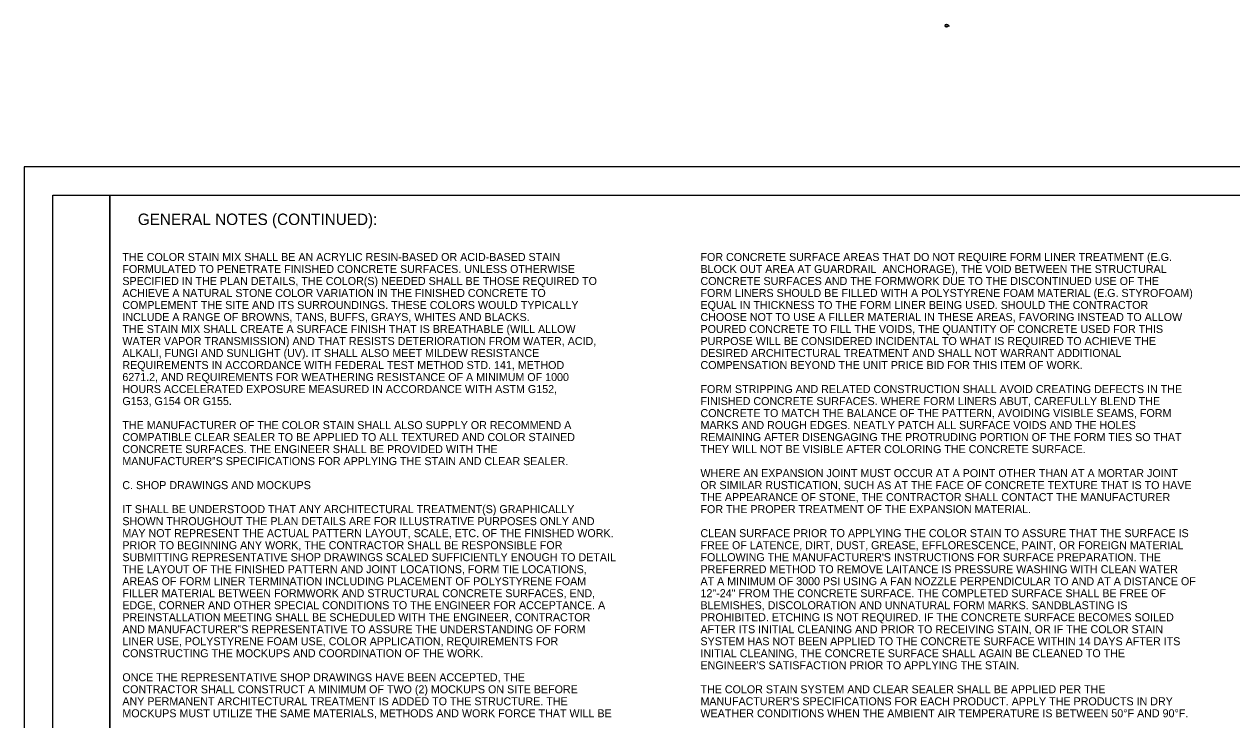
# Model space of a CAD drawing. Extents: x 0 to 442, y -31 to 24.
# Drawn here: x 0 to 21.13, y 12.33 to 24.49 of the extents above; entities that cross this region are included whole.
import ezdxf

# ---------------------------------------------------------------- set-up
doc = ezdxf.new("R2010")
doc.units = 0
for name, color, linetype in [('Default', 7, 'Continuous'), ('SH_Border', 7, 'Continuous'), ('SH_Cut_Line', 7, 'Continuous'), ('SH_Text', 7, 'Continuous')]:
    doc.layers.add(name, color=color, linetype=linetype)

msp = doc.modelspace()

# ---------------------------------------------------------------- linework, layer by layer
at = {"layer": 'Default'}
for p, q in [((16.11, 24.467), (16.163, 24.467)), ((16.137, 24.467), (16.186, 24.467))]:
    msp.add_line(p, q, dxfattribs=at)
msp.add_circle((16.137, 24.467), 0.026, dxfattribs=at)
at = {"layer": 'SH_Border'}
for points in [[(0.5, 21.5), (1.5, 21.5), (1.5, 0.5), (0.5, 0.5)], [(1.5, 21.5), (33.5, 21.5), (33.5, 0.5), (1.5, 0.5)]]:
    msp.add_lwpolyline(points, close=True, dxfattribs=at)
at = {"layer": 'SH_Cut_Line'}
msp.add_lwpolyline([(0, 0), (34, 0), (34, 22), (0, 22)], close=True, dxfattribs=at)

# ---------------------------------------------------------------- texts
at = {"layer": 'Default'}
for s, height, p in [('P.27', 0.00328, (16.132, 24.457)), ('1', 0.00328, (16.136, 24.474)), ('Drawing', 0.00328, (16.169, 24.474)), ('1:1', 0.00328, (16.169, 24.457)), ('THE COLOR STAIN MIX SHALL BE AN ACRYLIC RESIN-BASED OR ACID-BASED STAIN', 0.14, (1.718, 20.352)), ('FOR CONCRETE SURFACE AREAS THAT DO NOT REQUIRE FORM LINER TREATMENT (E.G.', 0.14, (11.831, 20.352)), ('FORMULATED TO PENETRATE FINISHED CONCRETE SURFACES. UNLESS OTHERWISE', 0.14, (1.718, 20.142)), ('BLOCK OUT AREA AT GUARDRAIL  ANCHORAGE), THE VOID BETWEEN THE STRUCTURAL ', 0.14, (11.831, 20.142)), ('SPECIFIED IN THE PLAN DETAILS, THE COLOR(S) NEEDED SHALL BE THOSE REQUIRED TO ', 0.14, (1.718, 19.932)), ('CONCRETE SURFACES AND THE FORMWORK DUE TO THE DISCONTINUED USE OF THE ', 0.14, (11.831, 19.932)), ('ACHIEVE A NATURAL STONE COLOR VARIATION IN THE FINISHED CONCRETE TO', 0.14, (1.718, 19.722)), ('FORM LINERS SHOULD BE FILLED WITH A POLYSTYRENE FOAM MATERIAL (E.G. STYROFOAM) ', 0.14, (11.831, 19.722)), ('COMPLEMENT THE SITE AND ITS SURROUNDINGS. THESE COLORS WOULD TYPICALLY', 0.14, (1.718, 19.512)), ('EQUAL IN THICKNESS TO THE FORM LINER BEING USED. SHOULD THE CONTRACTOR ', 0.14, (11.831, 19.512)), ('INCLUDE A RANGE OF BROWNS, TANS, BUFFS, GRAYS, WHITES AND BLACKS.', 0.14, (1.718, 19.302)), ('CHOOSE NOT TO USE A FILLER MATERIAL IN THESE AREAS, FAVORING INSTEAD TO ALLOW ', 0.14, (11.831, 19.302)), ('THE STAIN MIX SHALL CREATE A SURFACE FINISH THAT IS BREATHABLE (WILL ALLOW', 0.14, (1.718, 19.092)), ('POURED CONCRETE TO FILL THE VOIDS, THE QUANTITY OF CONCRETE USED FOR THIS ', 0.14, (11.831, 19.092)), ('WATER VAPOR TRANSMISSION) AND THAT RESISTS DETERIORATION FROM WATER, ACID,', 0.14, (1.718, 18.882)), ('PURPOSE WILL BE CONSIDERED INCIDENTAL TO WHAT IS REQUIRED TO ACHIEVE THE ', 0.14, (11.831, 18.882)), ('ALKALI, FUNGI AND SUNLIGHT (UV). IT SHALL ALSO MEET MILDEW RESISTANCE', 0.14, (1.718, 18.672)), ('DESIRED ARCHITECTURAL TREATMENT AND SHALL NOT WARRANT ADDITIONAL ', 0.14, (11.831, 18.672)), ('REQUIREMENTS IN ACCORDANCE WITH FEDERAL TEST METHOD STD. 141, METHOD', 0.14, (1.718, 18.462)), ('COMPENSATION BEYOND THE UNIT PRICE BID FOR THIS ITEM OF WORK.', 0.14, (11.831, 18.462)), ('6271.2, AND REQUIREMENTS FOR WEATHERING RESISTANCE OF A MINIMUM OF 1000', 0.14, (1.718, 18.252)), ('HOURS ACCELERATED EXPOSURE MEASURED IN ACCORDANCE WITH ASTM G152,', 0.14, (1.718, 18.042)), ('FORM STRIPPING AND RELATED CONSTRUCTION SHALL AVOID CREATING DEFECTS IN THE ', 0.14, (11.831, 18.042)), ('G153, G154 OR G155.', 0.14, (1.718, 17.832)), ('FINISHED CONCRETE SURFACES. WHERE FORM LINERS ABUT, CAREFULLY BLEND THE ', 0.14, (11.831, 17.832)), ('CONCRETE TO MATCH THE BALANCE OF THE PATTERN, AVOIDING VISIBLE SEAMS, FORM', 0.14, (11.831, 17.622)), ('THE MANUFACTURER OF THE COLOR STAIN SHALL ALSO SUPPLY OR RECOMMEND A', 0.14, (1.718, 17.412)), ('MARKS AND ROUGH EDGES. NEATLY PATCH ALL SURFACE VOIDS AND THE HOLES ', 0.14, (11.831, 17.412)), ('COMPATIBLE CLEAR SEALER TO BE APPLIED TO ALL TEXTURED AND COLOR STAINED', 0.14, (1.718, 17.202)), ('REMAINING AFTER DISENGAGING THE PROTRUDING PORTION OF THE FORM TIES SO THAT ', 0.14, (11.831, 17.202)), ('CONCRETE SURFACES. THE ENGINEER SHALL BE PROVIDED WITH THE', 0.14, (1.718, 16.992)), ('THEY WILL NOT BE VISIBLE AFTER COLORING THE CONCRETE SURFACE.', 0.14, (11.831, 16.992)), ('MANUFACTURER‟S SPECIFICATIONS FOR APPLYING THE STAIN AND CLEAR SEALER.', 0.14, (1.718, 16.782)), ('WHERE AN EXPANSION JOINT MUST OCCUR AT A POINT OTHER THAN AT A MORTAR JOINT ', 0.14, (11.831, 16.572)), ('C. SHOP DRAWINGS AND MOCKUPS', 0.14, (1.718, 16.362)), ('OR SIMILAR RUSTICATION, SUCH AS AT THE FACE OF CONCRETE TEXTURE THAT IS TO HAVE ', 0.14, (11.831, 16.362)), ('THE APPEARANCE OF STONE, THE CONTRACTOR SHALL CONTACT THE MANUFACTURER ', 0.14, (11.831, 16.152)), ('IT SHALL BE UNDERSTOOD THAT ANY ARCHITECTURAL TREATMENT(S) GRAPHICALLY ', 0.14, (1.718, 15.942)), ('FOR THE PROPER TREATMENT OF THE EXPANSION MATERIAL.', 0.14, (11.831, 15.942)), ('SHOWN THROUGHOUT THE PLAN DETAILS ARE FOR ILLUSTRATIVE PURPOSES ONLY AND ', 0.14, (1.718, 15.732)), ('MAY NOT REPRESENT THE ACTUAL PATTERN LAYOUT, SCALE, ETC. OF THE FINISHED WORK. ', 0.14, (1.718, 15.522)), ('CLEAN SURFACE PRIOR TO APPLYING THE COLOR STAIN TO ASSURE THAT THE SURFACE IS ', 0.14, (11.831, 15.522)), ('PRIOR TO BEGINNING ANY WORK, THE CONTRACTOR SHALL BE RESPONSIBLE FOR ', 0.14, (1.718, 15.312)), ('FREE OF LATENCE, DIRT, DUST, GREASE, EFFLORESCENCE, PAINT, OR FOREIGN MATERIAL ', 0.14, (11.831, 15.312)), ('SUBMITTING REPRESENTATIVE SHOP DRAWINGS SCALED SUFFICIENTLY ENOUGH TO DETAIL ', 0.14, (1.718, 15.102)), ("FOLLOWING THE MANUFACTURER'S INSTRUCTIONS FOR SURFACE PREPARATION. THE ", 0.14, (11.831, 15.102)), ('THE LAYOUT OF THE FINISHED PATTERN AND JOINT LOCATIONS, FORM TIE LOCATIONS, ', 0.14, (1.718, 14.892)), ('PREFERRED METHOD TO REMOVE LAITANCE IS PRESSURE WASHING WITH CLEAN WATER ', 0.14, (11.831, 14.892)), ('AREAS OF FORM LINER TERMINATION INCLUDING PLACEMENT OF POLYSTYRENE FOAM ', 0.14, (1.718, 14.682)), ('AT A MINIMUM OF 3000 PSI USING A FAN NOZZLE PERPENDICULAR TO AND AT A DISTANCE OF ', 0.14, (11.831, 14.682)), ('FILLER MATERIAL BETWEEN FORMWORK AND STRUCTURAL CONCRETE SURFACES, END, ', 0.14, (1.718, 14.472)), ('12"-24" FROM THE CONCRETE SURFACE. THE COMPLETED SURFACE SHALL BE FREE OF ', 0.14, (11.831, 14.472)), ('EDGE, CORNER AND OTHER SPECIAL CONDITIONS TO THE ENGINEER FOR ACCEPTANCE. A ', 0.14, (1.718, 14.262)), ('BLEMISHES, DISCOLORATION AND UNNATURAL FORM MARKS. SANDBLASTING IS ', 0.14, (11.831, 14.262)), ('PREINSTALLATION MEETING SHALL BE SCHEDULED WITH THE ENGINEER, CONTRACTOR ', 0.14, (1.718, 14.052)), ('PROHIBITED. ETCHING IS NOT REQUIRED. IF THE CONCRETE SURFACE BECOMES SOILED ', 0.14, (11.831, 14.052)), ('AND MANUFACTURER‟S REPRESENTATIVE TO ASSURE THE UNDERSTANDING OF FORM ', 0.14, (1.718, 13.842)), ('AFTER ITS INITIAL CLEANING AND PRIOR TO RECEIVING STAIN, OR IF THE COLOR STAIN ', 0.14, (11.831, 13.842)), ('LINER USE, POLYSTYRENE FOAM USE, COLOR APPLICATION, REQUIREMENTS FOR ', 0.14, (1.718, 13.632)), ('SYSTEM HAS NOT BEEN APPLIED TO THE CONCRETE SURFACE WITHIN 14 DAYS AFTER ITS ', 0.14, (11.831, 13.632)), ('CONSTRUCTING THE MOCKUPS AND COORDINATION OF THE WORK.', 0.14, (1.718, 13.422)), ('INITIAL CLEANING, THE CONCRETE SURFACE SHALL AGAIN BE CLEANED TO THE ', 0.14, (11.831, 13.422)), ("ENGINEER'S SATISFACTION PRIOR TO APPLYING THE STAIN.", 0.14, (11.831, 13.212)), ('ONCE THE REPRESENTATIVE SHOP DRAWINGS HAVE BEEN ACCEPTED, THE', 0.14, (1.718, 13.002)), ('CONTRACTOR SHALL CONSTRUCT A MINIMUM OF TWO (2) MOCKUPS ON SITE BEFORE', 0.14, (1.718, 12.792)), ('THE COLOR STAIN SYSTEM AND CLEAR SEALER SHALL BE APPLIED PER THE ', 0.14, (11.831, 12.792)), ('ANY PERMANENT ARCHITECTURAL TREATMENT IS ADDED TO THE STRUCTURE. THE', 0.14, (1.718, 12.582)), ("MANUFACTURER'S SPECIFICATIONS FOR EACH PRODUCT. APPLY THE PRODUCTS IN DRY ", 0.14, (11.831, 12.582)), ('MOCKUPS MUST UTILIZE THE SAME MATERIALS, METHODS AND WORK FORCE THAT WILL BE ', 0.14, (1.718, 12.372)), ('WEATHER CONDITIONS WHEN THE AMBIENT AIR TEMPERATURE IS BETWEEN 50°F AND 90°F. ', 0.14, (11.831, 12.372))]:
    msp.add_text(s, height=height, dxfattribs=at).set_placement(p)
at = {"layer": 'SH_Text'}
msp.add_text('GENERAL NOTES (CONTINUED):', height=0.2, rotation=0, dxfattribs=at).set_placement((1.988, 20.981))

doc.saveas('drawing.dxf')
